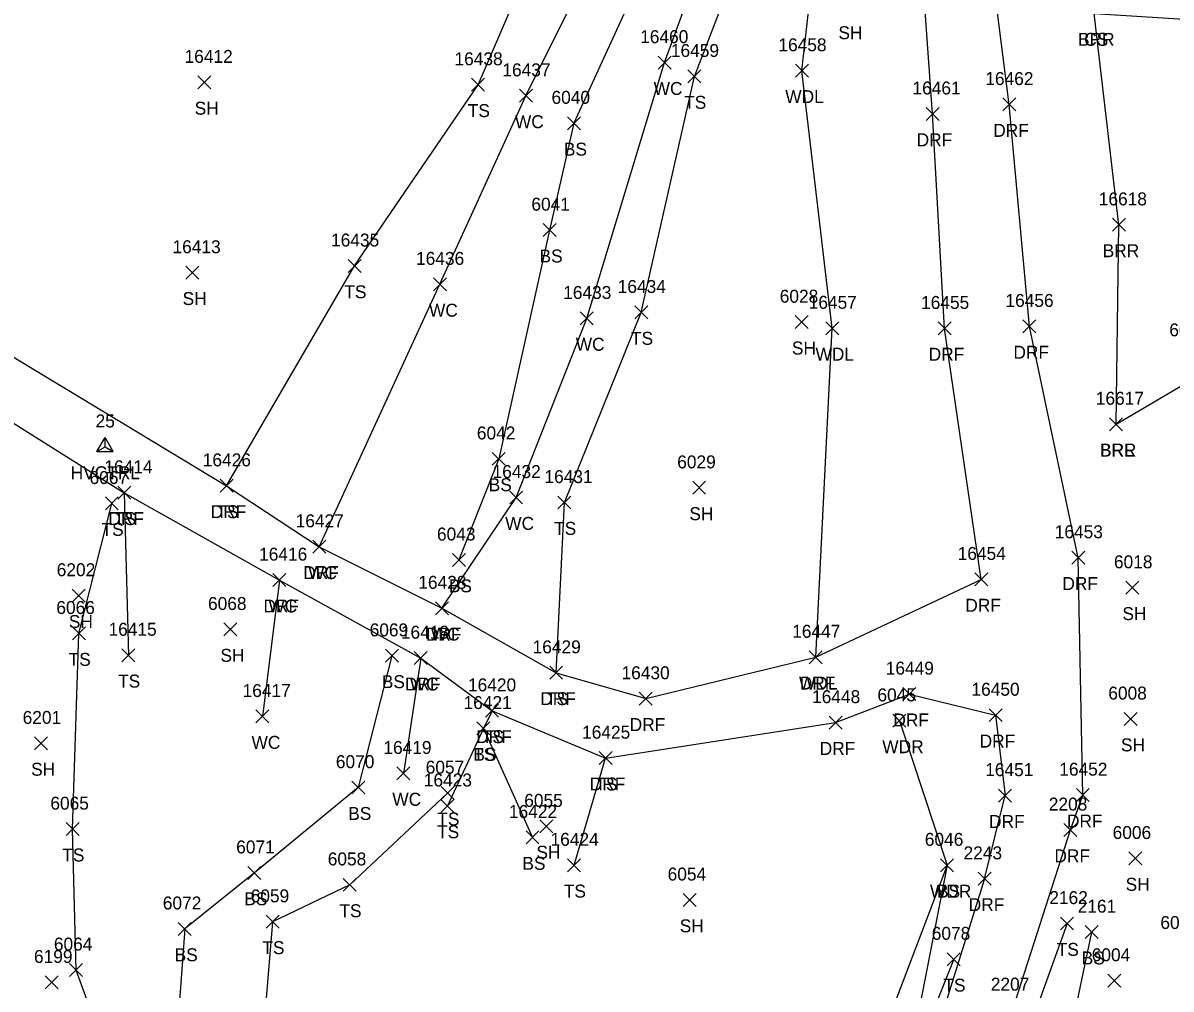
# Model space of a CAD drawing. Extents: x 1482574 to 1485769, y 580696 to 595649.
# Drawn here: x 1484548.8 to 1484726, y 582851.2 to 583000.4 of the extents above; entities that cross this region are included whole.
import ezdxf

# ---------------------------------------------------------------- set-up
doc = ezdxf.new("R2010")
doc.units = 0
for name, color, linetype in [('C_A', 7, 'Continuous'), ('C_I', 7, 'Continuous'), ('CPSM', 7, 'Continuous'), ('L_A', 7, 'Continuous'), ('L_I', 7, 'Continuous'), ('L_TIC', 7, 'Continuous'), ('LABL', 7, 'Continuous'), ('LAWA', 7, 'Continuous'), ('LAWE', 7, 'Continuous'), ('LELB', 7, 'Continuous'), ('R_A', 7, 'Continuous'), ('R_I', 7, 'Continuous'), ('R_TIC', 7, 'Continuous'), ('RDF', 7, 'Continuous')]:
    doc.layers.add(name, color=color, linetype=linetype)

msp = doc.modelspace()

# ---------------------------------------------------------------- linework, layer by layer
at = {"layer": 'CPSM'}
for p, q in [((1484560.18, 582934.19), (1484561.43, 582936.36)), ((1484562.68, 582934.19), (1484561.43, 582936.36)), ((1484561.43, 582934.92), (1484561.43, 582936.36)), ((1484560.18, 582934.19), (1484561.43, 582934.92)), ((1484560.18, 582934.19), (1484562.68, 582934.19)), ((1484561.43, 582934.92), (1484561.43, 582934.92)), ((1484561.43, 582934.92), (1484562.68, 582934.19))]:
    msp.add_line(p, q, dxfattribs=at)
at = {"layer": 'L_TIC'}
for points in [[(1484646.84, 582993.26), (1484648.84, 582995.26)], [(1484648.84, 582993.26), (1484646.84, 582995.26)], [(1484651.44, 582991.12), (1484653.44, 582993.12)], [(1484653.44, 582991.12), (1484651.44, 582993.12)], [(1484668.04, 582992), (1484670.04, 582994)], [(1484670.04, 582992), (1484668.04, 582994)], [(1484575.78, 582990.21), (1484577.78, 582992.21)], [(1484577.78, 582990.21), (1484575.78, 582992.21)], [(1484618.03, 582989.84), (1484620.03, 582991.84)], [(1484620.03, 582989.84), (1484618.03, 582991.84)], [(1484625.41, 582988.13), (1484627.41, 582990.13)], [(1484627.41, 582988.13), (1484625.41, 582990.13)], [(1484632.84, 582983.89), (1484634.84, 582985.89)], [(1484634.84, 582983.89), (1484632.84, 582985.89)], [(1484716.99, 582968.21), (1484718.99, 582970.21)], [(1484718.99, 582968.21), (1484716.99, 582970.21)], [(1484629.08, 582967.39), (1484631.08, 582969.39)], [(1484631.08, 582967.39), (1484629.08, 582969.39)], [(1484573.92, 582960.82), (1484575.92, 582962.82)], [(1484575.92, 582960.82), (1484573.92, 582962.82)], [(1484598.97, 582961.86), (1484600.97, 582963.86)], [(1484600.97, 582961.86), (1484598.97, 582963.86)], [(1484612.14, 582959.02), (1484614.14, 582961.02)], [(1484614.14, 582959.02), (1484612.14, 582961.02)], [(1484634.81, 582953.76), (1484636.81, 582955.76)], [(1484636.81, 582953.76), (1484634.81, 582955.76)], [(1484643.23, 582954.68), (1484645.23, 582956.68)], [(1484645.23, 582954.68), (1484643.23, 582956.68)], [(1484667.99, 582953.18), (1484669.99, 582955.18)], [(1484669.99, 582953.18), (1484667.99, 582955.18)], [(1484672.71, 582952.24), (1484674.71, 582954.24)], [(1484674.71, 582952.24), (1484672.71, 582954.24)], [(1484716.53, 582937.42), (1484718.53, 582939.42)], [(1484718.53, 582937.42), (1484716.53, 582939.42)], [(1484716.53, 582937.42), (1484718.53, 582939.42)], [(1484718.53, 582937.42), (1484716.53, 582939.42)], [(1484621.23, 582932.07), (1484623.23, 582934.07)], [(1484623.23, 582932.07), (1484621.23, 582934.07)], [(1484563.4, 582926.84), (1484565.4, 582928.84)], [(1484565.4, 582926.84), (1484563.4, 582928.84)], [(1484579.21, 582927.91), (1484581.21, 582929.91)], [(1484581.21, 582927.91), (1484579.21, 582929.91)], [(1484652.17, 582927.6), (1484654.17, 582929.6)], [(1484654.17, 582927.6), (1484652.17, 582929.6)], [(1484561.48, 582925.18), (1484563.48, 582927.18)], [(1484563.48, 582925.18), (1484561.48, 582927.18)], [(1484623.91, 582926.1), (1484625.91, 582928.1)], [(1484625.91, 582926.1), (1484623.91, 582928.1)], [(1484631.36, 582925.33), (1484633.36, 582927.33)], [(1484633.36, 582925.33), (1484631.36, 582927.33)], [(1484593.5, 582918.5), (1484595.5, 582920.5)], [(1484595.5, 582918.5), (1484593.5, 582920.5)], [(1484615.07, 582916.46), (1484617.07, 582918.46)], [(1484617.07, 582916.46), (1484615.07, 582918.46)], [(1484587.35, 582913.35), (1484589.35, 582915.35)], [(1484589.35, 582913.35), (1484587.35, 582915.35)], [(1484556.36, 582910.95), (1484558.36, 582912.95)], [(1484558.36, 582910.95), (1484556.36, 582912.95)], [(1484719.03, 582912.17), (1484721.03, 582914.17)], [(1484721.03, 582912.17), (1484719.03, 582914.17)], [(1484612.44, 582909), (1484614.44, 582911)], [(1484614.44, 582909), (1484612.44, 582911)], [(1484579.76, 582905.73), (1484581.76, 582907.73)], [(1484581.76, 582905.73), (1484579.76, 582907.73)], [(1484556.4, 582905.11), (1484558.4, 582907.11)], [(1484558.4, 582905.11), (1484556.4, 582907.11)], [(1484564.04, 582901.75), (1484566.04, 582903.75)], [(1484566.04, 582901.75), (1484564.04, 582903.75)], [(1484604.73, 582901.66), (1484606.73, 582903.66)], [(1484606.73, 582901.66), (1484604.73, 582903.66)], [(1484609.18, 582901.3), (1484611.18, 582903.3)], [(1484611.18, 582901.3), (1484609.18, 582903.3)], [(1484670.16, 582901.44), (1484672.16, 582903.44)], [(1484672.16, 582901.44), (1484670.16, 582903.44)], [(1484630.09, 582899.04), (1484632.09, 582901.04)], [(1484632.09, 582899.04), (1484630.09, 582901.04)], [(1484620.2, 582893.17), (1484622.2, 582895.17)], [(1484622.2, 582893.17), (1484620.2, 582895.17)], [(1484584.74, 582892.29), (1484586.74, 582894.29)], [(1484586.74, 582892.29), (1484584.74, 582894.29)], [(1484683.08, 582891.62), (1484685.08, 582893.62)], [(1484685.08, 582891.62), (1484683.08, 582893.62)], [(1484718.81, 582891.9), (1484720.81, 582893.9)], [(1484720.81, 582891.9), (1484718.81, 582893.9)], [(1484618.86, 582890.44), (1484620.86, 582892.44)], [(1484620.86, 582890.44), (1484618.86, 582892.44)], [(1484618.86, 582890.44), (1484620.86, 582892.44)], [(1484620.86, 582890.44), (1484618.86, 582892.44)], [(1484550.53, 582888.14), (1484552.53, 582890.14)], [(1484552.53, 582888.14), (1484550.53, 582890.14)], [(1484637.73, 582885.86), (1484639.73, 582887.86)], [(1484639.73, 582885.86), (1484637.73, 582887.86)], [(1484606.49, 582883.5), (1484608.49, 582885.5)], [(1484608.49, 582883.5), (1484606.49, 582885.5)], [(1484599.54, 582881.32), (1484601.54, 582883.31)], [(1484601.54, 582881.32), (1484599.54, 582883.31)], [(1484613.32, 582880.46), (1484615.32, 582882.46)], [(1484615.32, 582880.46), (1484613.32, 582882.46)], [(1484613.29, 582878.48), (1484615.29, 582880.48)], [(1484615.29, 582878.48), (1484613.29, 582880.48)], [(1484555.42, 582874.9), (1484557.42, 582876.9)], [(1484557.42, 582874.9), (1484555.42, 582876.9)], [(1484626.43, 582873.61), (1484628.43, 582875.61)], [(1484628.43, 582873.61), (1484626.43, 582875.61)], [(1484628.55, 582875.33), (1484630.55, 582877.33)], [(1484630.55, 582875.33), (1484628.55, 582877.33)], [(1484719.53, 582870.37), (1484721.53, 582872.37)], [(1484721.53, 582870.37), (1484719.53, 582872.37)], [(1484632.86, 582869.32), (1484634.86, 582871.32)], [(1484634.86, 582869.32), (1484632.86, 582871.32)], [(1484690.45, 582869.31), (1484692.45, 582871.31)], [(1484692.45, 582869.31), (1484690.45, 582871.31)], [(1484690.45, 582869.31), (1484692.45, 582871.31)], [(1484692.45, 582869.31), (1484690.45, 582871.31)], [(1484583.5, 582868.14), (1484585.5, 582870.14)], [(1484585.5, 582868.14), (1484583.5, 582870.14)], [(1484598.21, 582866.29), (1484600.21, 582868.29)], [(1484600.21, 582866.29), (1484598.21, 582868.29)], [(1484650.68, 582863.96), (1484652.68, 582865.96)], [(1484652.68, 582863.96), (1484650.68, 582865.96)], [(1484572.74, 582859.49), (1484574.74, 582861.49)], [(1484574.74, 582859.49), (1484572.74, 582861.49)], [(1484586.31, 582860.59), (1484588.31, 582862.59)], [(1484588.31, 582860.59), (1484586.31, 582862.59)], [(1484708.97, 582860.32), (1484710.97, 582862.32)], [(1484710.97, 582860.32), (1484708.97, 582862.32)], [(1484712.79, 582859), (1484714.79, 582861)], [(1484714.79, 582859), (1484712.79, 582861)], [(1484691.47, 582854.8), (1484693.47, 582856.8)], [(1484693.47, 582854.8), (1484691.47, 582856.8)], [(1484555.96, 582853.14), (1484557.96, 582855.14)], [(1484557.96, 582853.14), (1484555.96, 582855.14)], [(1484552.21, 582851.23), (1484554.21, 582853.23)], [(1484554.21, 582851.23), (1484552.21, 582853.23)], [(1484716.25, 582851.49), (1484718.25, 582853.49)], [(1484718.25, 582851.49), (1484716.25, 582853.49)]]:
    msp.add_lwpolyline(points, dxfattribs=at)
at = {"layer": 'LABL'}
for points in [[(1484717.53, 582938.42), (1484717.99, 582969.21), (1484714.17, 583001.85), (1484742.03, 583000.07), (1484770.64, 582982.57), (1484748.06, 582956.38)], [(1484717.53, 582938.42), (1484748.06, 582956.38)]]:
    msp.add_lwpolyline(points, dxfattribs=at)
at = {"layer": 'LAWA'}
for points in [[(1484671.16, 582902.44), (1484673.71, 582953.24), (1484669.04, 582993), (1484673.27, 583031.01), (1484670.32, 583075.03), (1484676.97, 583118.82), (1484679.39, 583135.46), (1484646.17, 583168.07), (1484609.78, 583229.2), (1484574.48, 583271.72), (1484553.61, 583304.37), (1484548.06, 583341.16), (1484539.98, 583379.14), (1484531.9, 583400.38), (1484513.75, 583410.43), (1484483.35, 583401.75), (1484453.6, 583388.88)], [(1484684.08, 582892.62), (1484691.45, 582870.31), (1484684.98, 582837.02), (1484672.94, 582819.7), (1484659.5, 582810.62), (1484651.42, 582810.44), (1484635.18, 582806.08), (1484626.57, 582802.92), (1484609.61, 582799.21), (1484592.86, 582794.65)]]:
    msp.add_lwpolyline(points, dxfattribs=at)
at = {"layer": 'LAWE'}
for points in [[(1484613.44, 582910), (1484624.91, 582927.1), (1484635.81, 582954.76), (1484647.84, 582994.26), (1484661.58, 583031.79), (1484660.44, 583072.06), (1484658.15, 583106.61), (1484645.73, 583125.29), (1484617.99, 583163.5), (1484584.97, 583218.29), (1484555.15, 583259.68), (1484531.72, 583297.18), (1484518.61, 583320.77), (1484520.31, 583354.96), (1484523.08, 583375.32), (1484509.84, 583380.79), (1484501.97, 583358.62), (1484490.54, 583338.42), (1484488.75, 583334.81), (1484501.06, 583309.01), (1484513.98, 583289.05), (1484537.48, 583249.69), (1484560.05, 583217.91), (1484581.57, 583186.56)], [(1484594.5, 582919.5), (1484613.14, 582960.02), (1484626.41, 582989.13), (1484648.18, 583032.76), (1484646.87, 583075.35), (1484626.42, 583113.68), (1484599.04, 583156.53), (1484581.57, 583186.56)], [(1484588.35, 582914.35), (1484585.74, 582893.29)], [(1484610.18, 582902.3), (1484607.49, 582884.5)]]:
    msp.add_lwpolyline(points, dxfattribs=at)
at = {"layer": 'LELB'}
for points in [[(1484631.09, 582900.04), (1484632.36, 582926.33), (1484644.23, 582955.68), (1484652.44, 582992.12), (1484667.72, 583031.83), (1484670.32, 583075.03), (1484666.12, 583110.27), (1484653.54, 583126.66), (1484626.6, 583168.4), (1484594.63, 583226.14), (1484561.25, 583267.44), (1484537.65, 583300.73), (1484529.49, 583326.89), (1484527.39, 583353.89), (1484528.28, 583374.18), (1484531.9, 583400.38)], [(1484580.21, 582928.91), (1484599.97, 582962.86), (1484619.03, 582990.84), (1484637.76, 583034.4), (1484637.2, 583073), (1484615.42, 583113.4), (1484594.8, 583155.59), (1484575.44, 583185.35)], [(1484655.03, 583110.56), (1484654.05, 583042.48), (1484648.15, 583016.24), (1484633.84, 582984.89), (1484630.08, 582968.39), (1484622.23, 582933.07), (1484616.07, 582917.46)], [(1484564.4, 582927.84), (1484565.04, 582902.75)], [(1484614.32, 582881.46), (1484599.21, 582867.29), (1484587.31, 582861.59), (1484585.78, 582843.54), (1484572.93, 582826.56), (1484564.78, 582829.5), (1484563.39, 582836.43), (1484556.96, 582854.14), (1484556.42, 582875.9), (1484557.4, 582906.11), (1484562.48, 582926.18)], [(1484605.73, 582902.66), (1484600.54, 582882.31), (1484584.5, 582869.14), (1484573.74, 582860.49), (1484572.16, 582838.93), (1484572.17, 582838.07), (1484566.33, 582833.47)], [(1484621.2, 582894.17), (1484619.86, 582891.44), (1484614.29, 582879.48)], [(1484619.86, 582891.44), (1484627.43, 582874.61)], [(1484633.86, 582870.32), (1484638.73, 582886.86)], [(1484691.45, 582870.31), (1484681.04, 582842.99), (1484670.53, 582829.17), (1484653.97, 582820.19), (1484634.92, 582814.8), (1484615.41, 582810.05)], [(1484709.97, 582861.32), (1484702.7, 582841.03), (1484695.81, 582824.64), (1484701.59, 582815.09)], [(1484744.77, 582819.3), (1484739.22, 582822.88), (1484737.33, 582823.37), (1484722.38, 582822.54), (1484705.56, 582824.88), (1484704.83, 582830.6), (1484710.43, 582844.02), (1484713.79, 582860)], [(1484692.47, 582855.8), (1484684.98, 582837.02)]]:
    msp.add_lwpolyline(points, dxfattribs=at)
at = {"layer": 'R_TIC'}
for points in [[(1484688.22, 582985.33), (1484690.22, 582987.33)], [(1484690.22, 582985.33), (1484688.22, 582987.33)], [(1484700.04, 582986.79), (1484702.04, 582988.79)], [(1484702.04, 582986.79), (1484700.04, 582988.79)], [(1484690.07, 582952.22), (1484692.07, 582954.22)], [(1484692.07, 582952.22), (1484690.07, 582954.22)], [(1484703.15, 582952.53), (1484705.15, 582954.53)], [(1484705.15, 582952.53), (1484703.15, 582954.53)], [(1484563.4, 582926.84), (1484565.4, 582928.84)], [(1484565.4, 582926.84), (1484563.4, 582928.84)], [(1484579.21, 582927.91), (1484581.21, 582929.91)], [(1484581.21, 582927.91), (1484579.21, 582929.91)], [(1484593.5, 582918.5), (1484595.5, 582920.5)], [(1484595.5, 582918.5), (1484593.5, 582920.5)], [(1484710.71, 582916.81), (1484712.71, 582918.81)], [(1484712.71, 582916.81), (1484710.71, 582918.81)], [(1484587.35, 582913.35), (1484589.35, 582915.35)], [(1484589.35, 582913.35), (1484587.35, 582915.35)], [(1484695.72, 582913.46), (1484697.72, 582915.46)], [(1484697.72, 582913.46), (1484695.72, 582915.46)], [(1484612.44, 582909), (1484614.44, 582911)], [(1484614.44, 582909), (1484612.44, 582911)], [(1484609.18, 582901.3), (1484611.18, 582903.3)], [(1484611.18, 582901.3), (1484609.18, 582903.3)], [(1484670.16, 582901.44), (1484672.16, 582903.44)], [(1484672.16, 582901.44), (1484670.16, 582903.44)], [(1484630.09, 582899.04), (1484632.09, 582901.04)], [(1484632.09, 582899.04), (1484630.09, 582901.04)], [(1484643.91, 582895.04), (1484645.91, 582897.04)], [(1484645.91, 582895.04), (1484643.91, 582897.04)], [(1484684.62, 582895.75), (1484686.62, 582897.75)], [(1484686.62, 582895.75), (1484684.62, 582897.75)], [(1484620.2, 582893.17), (1484622.2, 582895.17)], [(1484622.2, 582893.17), (1484620.2, 582895.17)], [(1484673.24, 582891.35), (1484675.24, 582893.35)], [(1484675.24, 582891.35), (1484673.24, 582893.35)], [(1484697.94, 582892.49), (1484699.94, 582894.49)], [(1484699.94, 582892.49), (1484697.94, 582894.49)], [(1484637.73, 582885.86), (1484639.73, 582887.86)], [(1484639.73, 582885.86), (1484637.73, 582887.86)], [(1484699.4, 582880.08), (1484701.4, 582882.08)], [(1484701.4, 582880.08), (1484699.4, 582882.08)], [(1484711.41, 582880.15), (1484713.41, 582882.15)], [(1484713.41, 582880.15), (1484711.41, 582882.15)], [(1484709.49, 582874.76), (1484711.49, 582876.76)], [(1484711.49, 582874.76), (1484709.49, 582876.76)], [(1484696.25, 582867.23), (1484698.25, 582869.23)], [(1484698.25, 582867.23), (1484696.25, 582869.23)]]:
    msp.add_lwpolyline(points, dxfattribs=at)
at = {"layer": 'RDF'}
for points in [[(1484430.95, 582982.72), (1484459.52, 582977.04), (1484492.26, 582973.15), (1484509.14, 582970.27), (1484523, 582963.42), (1484580.21, 582928.91), (1484594.5, 582919.5), (1484613.44, 582910), (1484631.09, 582900.04), (1484644.91, 582896.04), (1484671.16, 582902.44), (1484696.72, 582914.46), (1484691.07, 582953.22), (1484689.22, 582986.33), (1484686.12, 583029.68), (1484682.22, 583074.27), (1484683.92, 583119.13), (1484683.59, 583135.66), (1484680.92, 583152.23)], [(1484712.41, 582881.15), (1484711.71, 582917.81), (1484704.15, 582953.53), (1484701.04, 582987.79), (1484695.81, 583028.76), (1484695.28, 583076.22), (1484694.44, 583118.53), (1484696.9, 583136.82), (1484696.75, 583151.57), (1484680.92, 583152.23)], [(1484428.39, 582974.73), (1484458.56, 582968.76), (1484490.85, 582965.75), (1484506.56, 582962.61), (1484516.5, 582958.71), (1484533.62, 582947.17), (1484564.4, 582927.84), (1484588.35, 582914.35), (1484610.18, 582902.3), (1484621.2, 582894.17), (1484638.73, 582886.86), (1484674.24, 582892.35), (1484685.62, 582896.75), (1484698.94, 582893.49), (1484700.4, 582881.08)], [(1484697.25, 582868.23), (1484700.4, 582881.08)], [(1484710.49, 582875.76), (1484712.41, 582881.15)], [(1484694.94, 582807.9), (1484690, 582820.03), (1484701.54, 582847.96), (1484710.49, 582875.76)], [(1484697.25, 582868.23), (1484688.59, 582840.6), (1484675.62, 582819.01), (1484661.99, 582805.26)]]:
    msp.add_lwpolyline(points, dxfattribs=at)

# ---------------------------------------------------------------- texts
at = {"layer": 'C_A'}
msp.add_text('HVCTRL', height=2, dxfattribs=at).set_placement((1484556.13, 582929.92))
at = {"layer": 'C_I'}
msp.add_text('25', height=2, dxfattribs=at).set_placement((1484559.97, 582937.92))
at = {"layer": 'L_A'}
for s, p in [('SH', (1484674.67, 582997.87)), ('BRR', (1484711.66, 582996.85)), ('CS', (1484712.61, 582996.85)), ('WC', (1484646.14, 582989.26)), ('TS', (1484650.85, 582987.12)), ('WDL', (1484666.46, 582988)), ('SH', (1484575.27, 582986.21)), ('TS', (1484617.44, 582985.84)), ('WC', (1484624.72, 582984.13)), ('BS', (1484632.28, 582979.89)), ('BRR', (1484715.47, 582964.21)), ('BS', (1484628.52, 582963.39)), ('TS', (1484598.38, 582957.86)), ('SH', (1484573.41, 582956.82)), ('WC', (1484611.45, 582955.02)), ('TS', (1484642.64, 582950.68)), ('WC', (1484634.11, 582949.76)), ('SH', (1484667.48, 582949.18)), ('WDL', (1484671.13, 582948.24)), ('BRR', (1484715.02, 582933.42)), ('BRL', (1484715.08, 582933.42)), ('BS', (1484620.67, 582928.07)), ('TS', (1484578.62, 582923.91)), ('SH', (1484651.66, 582923.6)), ('TS', (1484562.81, 582922.84)), ('WC', (1484623.22, 582922.1)), ('TS', (1484560.89, 582921.18)), ('TS', (1484630.77, 582921.33)), ('WC', (1484592.8, 582914.5)), ('BS', (1484614.51, 582912.46)), ('WC', (1484586.66, 582909.35)), ('SH', (1484718.52, 582908.17)), ('SH', (1484555.84, 582906.95)), ('WC', (1484611.74, 582905)), ('TS', (1484555.81, 582901.11)), ('SH', (1484579.25, 582901.73)), ('TS', (1484563.45, 582897.75)), ('BS', (1484604.17, 582897.66)), ('WC', (1484608.49, 582897.3)), ('WDL', (1484668.58, 582897.44)), ('TS', (1484629.5, 582895.04)), ('WC', (1484584.05, 582888.29)), ('TS', (1484619.61, 582889.17)), ('SH', (1484718.29, 582887.9)), ('TS', (1484618.27, 582886.44)), ('BS', (1484618.3, 582886.44)), ('WDR', (1484681.44, 582887.62)), ('SH', (1484550.02, 582884.14)), ('TS', (1484637.14, 582881.86)), ('WC', (1484605.79, 582879.5)), ('BS', (1484598.98, 582877.31)), ('TS', (1484612.73, 582876.46)), ('TS', (1484612.7, 582874.48)), ('TS', (1484554.83, 582870.9)), ('SH', (1484628.04, 582871.33)), ('BS', (1484625.87, 582869.61)), ('TS', (1484632.27, 582865.32)), ('WDR', (1484688.81, 582865.31)), ('BS', (1484689.89, 582865.31)), ('SH', (1484719.02, 582866.37)), ('BS', (1484582.94, 582864.14)), ('TS', (1484597.62, 582862.29)), ('SH', (1484650.17, 582859.96)), ('TS', (1484585.72, 582856.59)), ('TS', (1484708.38, 582856.32)), ('BS', (1484572.18, 582855.49)), ('BS', (1484712.23, 582855)), ('TS', (1484690.88, 582850.8))]:
    msp.add_text(s, height=2, dxfattribs=at).set_placement(p)
at = {"layer": 'L_I'}
for s, p in [('16460', (1484644.06, 582997.26)), ('16458', (1484665.4, 582996)), ('16412', (1484573.71, 582994.21)), ('16459', (1484648.8, 582995.12)), ('16438', (1484615.39, 582993.84)), ('16437', (1484622.78, 582992.13)), ('6040', (1484630.37, 582987.89)), ('6041', (1484627.26, 582971.39)), ('16618', (1484714.87, 582972.21)), ('16435', (1484596.33, 582965.86)), ('16413', (1484571.85, 582964.82)), ('16436', (1484609.45, 582963.02)), ('16434', (1484640.59, 582958.68)), ('16433', (1484632.17, 582957.76)), ('6028', (1484665.61, 582957.18)), ('16457', (1484670.08, 582956.24)), ('6019', (1484725.76, 582951.99)), ('16617', (1484714.41, 582941.42)), ('16617', (1484714.41, 582941.42)), ('6042', (1484618.84, 582936.07)), ('16414', (1484561.33, 582930.84)), ('16426', (1484576.52, 582931.91)), ('6029', (1484649.78, 582931.6)), ('6067', (1484559.04, 582929.18)), ('16432', (1484621.27, 582930.1)), ('16431', (1484629.28, 582929.33)), ('16427', (1484590.86, 582922.5)), ('6043', (1484612.68, 582920.46)), ('16416', (1484585.22, 582917.35)), ('6018', (1484717.21, 582916.17)), ('6202', (1484553.97, 582914.95)), ('16428', (1484609.8, 582913)), ('6066', (1484553.91, 582909.11)), ('6068', (1484577.33, 582909.73)), ('16415', (1484561.97, 582905.75)), ('6069', (1484602.29, 582905.66)), ('16418', (1484607.11, 582905.3)), ('16447', (1484667.53, 582905.44)), ('16429', (1484627.45, 582903.04)), ('16420', (1484617.47, 582897.17)), ('16417', (1484582.67, 582896.29)), ('6045', (1484680.69, 582895.62)), ('6008', (1484716.34, 582895.9)), ('16421', (1484616.79, 582894.44)), ('16421', (1484616.79, 582894.44)), ('6201', (1484548.71, 582892.14)), ('16425', (1484635.09, 582889.86)), ('16419', (1484604.41, 582887.5)), ('6070', (1484597.07, 582885.31)), ('6057', (1484610.94, 582884.46)), ('16423', (1484610.65, 582882.48)), ('6065', (1484552.99, 582878.9)), ('6055', (1484626.16, 582879.33)), ('16422', (1484623.79, 582877.61)), ('6006', (1484717.01, 582874.37)), ('6071', (1484581.68, 582872.14)), ('16424', (1484630.22, 582873.32)), ('6046', (1484688.01, 582873.31)), ('6046', (1484688.01, 582873.31)), ('6058', (1484595.82, 582870.29)), ('6054', (1484648.3, 582867.96)), ('6072', (1484570.35, 582863.49)), ('6059', (1484583.92, 582864.59)), ('2162', (1484707.23, 582864.32)), ('2161', (1484711.61, 582863)), ('6005', (1484724.38, 582860.47)), ('6078', (1484689.08, 582858.8)), ('6064', (1484553.53, 582857.14)), ('6199', (1484550.46, 582855.23)), ('6004', (1484713.78, 582855.49))]:
    msp.add_text(s, height=2, dxfattribs=at).set_placement(p)
at = {"layer": 'R_A'}
for p in [(1484698.57, 582982.79), (1484686.75, 582981.33), (1484688.61, 582948.22), (1484701.69, 582948.53), (1484577.75, 582923.91), (1484561.94, 582922.84), (1484592.03, 582914.5), (1484709.25, 582912.81), (1484585.89, 582909.35), (1484694.26, 582909.46), (1484610.97, 582905), (1484607.72, 582897.3), (1484668.7, 582897.44), (1484628.63, 582895.04), (1484683.15, 582891.75), (1484642.44, 582891.04), (1484618.73, 582889.17), (1484696.47, 582888.49), (1484671.78, 582887.35), (1484636.27, 582881.86), (1484697.93, 582876.08), (1484709.95, 582876.15), (1484708.02, 582870.76), (1484694.79, 582863.23)]:
    msp.add_text('DRF', height=2, dxfattribs=at).set_placement(p)
at = {"layer": 'R_I'}
for s, p in [('16462', (1484697.35, 582990.79)), ('16461', (1484686.1, 582989.33)), ('16455', (1484687.43, 582956.22)), ('16456', (1484700.46, 582956.53)), ('16414', (1484561.33, 582930.84)), ('16426', (1484576.52, 582931.91)), ('16427', (1484590.86, 582922.5)), ('16453', (1484708.07, 582920.81)), ('16416', (1484585.22, 582917.35)), ('16454', (1484693.08, 582917.46)), ('16428', (1484609.8, 582913)), ('16418', (1484607.11, 582905.3)), ('16447', (1484667.53, 582905.44)), ('16429', (1484627.45, 582903.04)), ('16430', (1484641.18, 582899.04)), ('16449', (1484681.97, 582899.75)), ('16420', (1484617.47, 582897.17)), ('16448', (1484670.6, 582895.35)), ('16450', (1484695.21, 582896.49)), ('16425', (1484635.09, 582889.86)), ('16451', (1484697.33, 582884.08)), ('16452', (1484708.77, 582884.15)), ('2208', (1484707.15, 582878.76)), ('2243', (1484693.99, 582871.23)), ('2207', (1484698.2, 582850.96))]:
    msp.add_text(s, height=2, dxfattribs=at).set_placement(p)

doc.saveas('drawing.dxf')
